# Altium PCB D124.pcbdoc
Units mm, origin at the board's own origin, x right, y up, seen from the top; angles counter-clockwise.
Board outline 29.56 x 21.95 mm, 2 copper layers (Top Layer, Bottom Layer); 1 components, 0 nets, 12 pads, 0 vias.
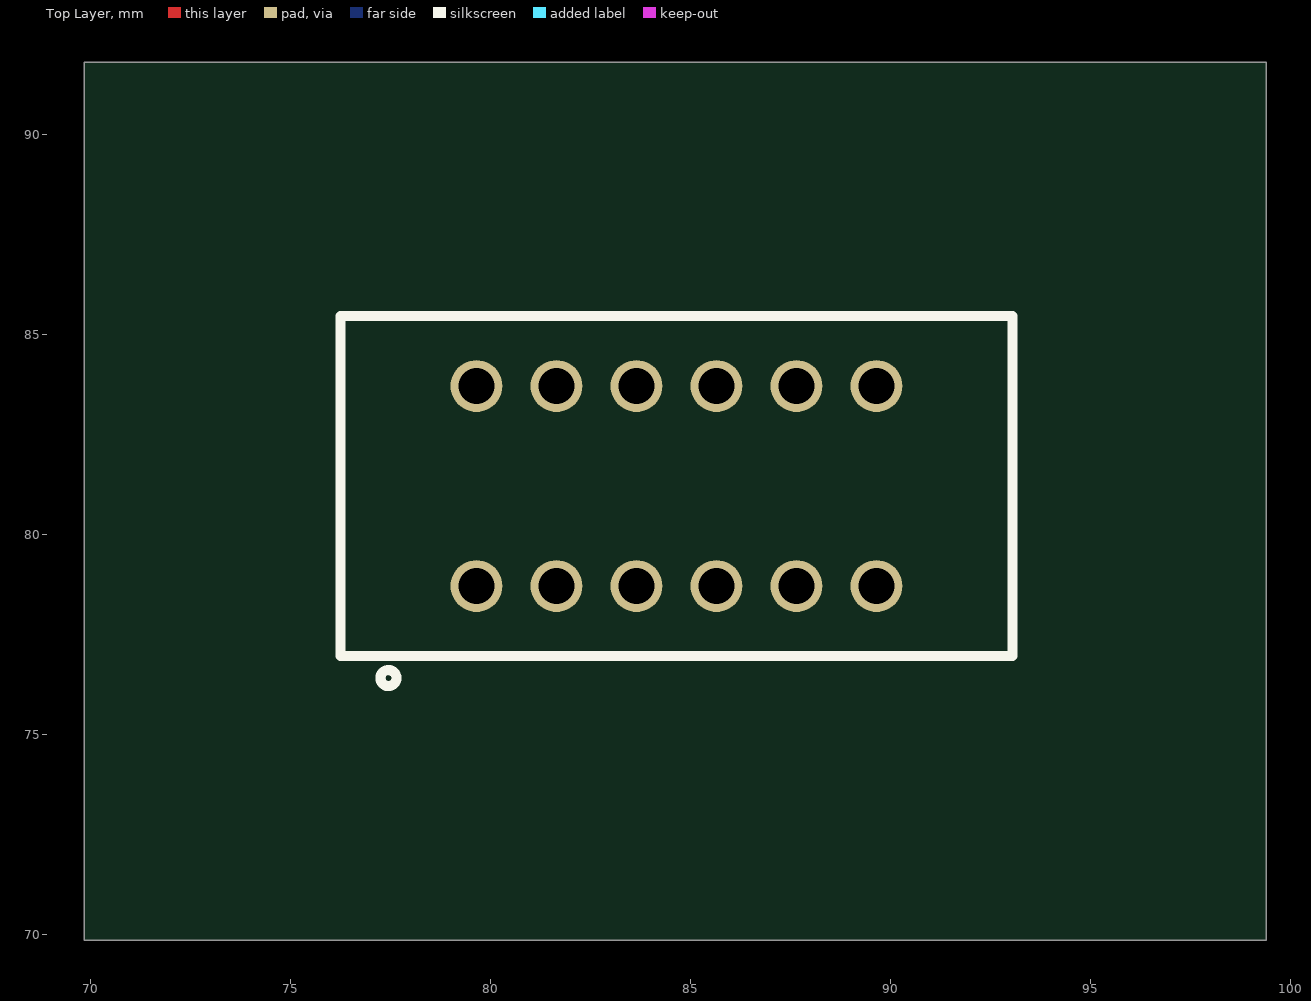
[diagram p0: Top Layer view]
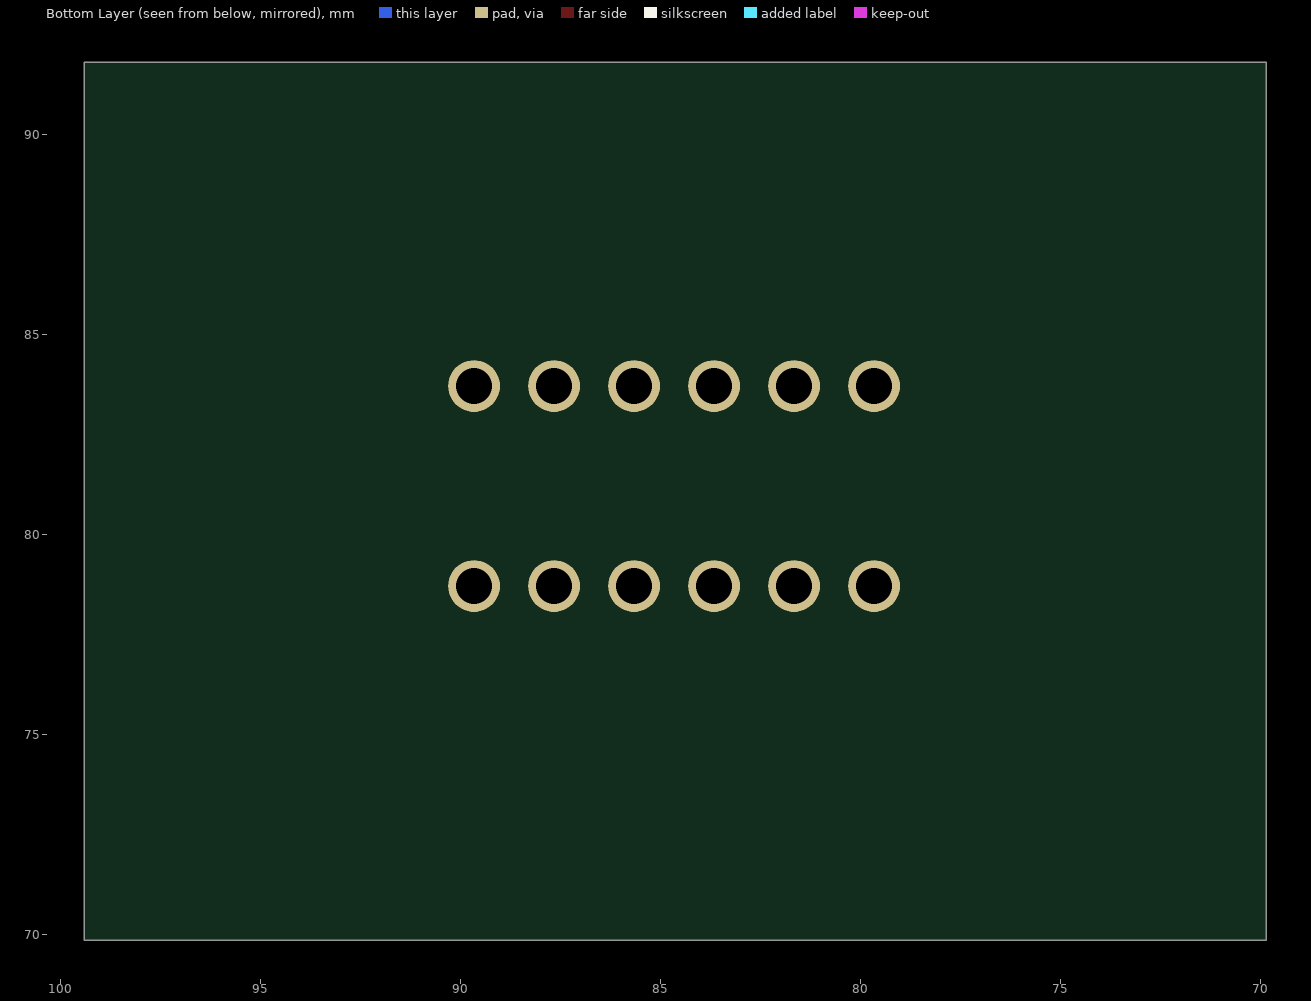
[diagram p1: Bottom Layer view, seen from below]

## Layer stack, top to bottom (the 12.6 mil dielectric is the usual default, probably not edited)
Top Layer: signal copper (thickness not stored)
Dielectric: dielectric 0.32, FR-4, Dk 4.8
Bottom Layer: signal copper (thickness not stored)

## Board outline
99.41,69.85 69.85,69.85 69.85,91.8 99.41,91.8

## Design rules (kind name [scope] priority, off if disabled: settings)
BoardOutlineClearance safeClearance [All] p0: genericclearance=0.254 ignorepadtopadclearanceinfootprint=FALSE except(0: Arc-SplitContinuation Track-SplitContinuation SMDPad-SplitContinuation THPad-SplitContinuation Via-SplitContinuation Fill-SplitContinuation Poly-SplitContinuation Region-SplitContinuation Text-SplitContinuation; 0.152: Track-CutoutEdge SMDPad-CutoutEdge THPad-CutoutEdge Via-CutoutEdge Fill-CutoutEdge Region-CutoutEdge; 0.3: Track-OutlineEdge SMDPad-OutlineEdge THPad-OutlineEdge Via-OutlineEdge Fill-OutlineEdge Region-OutlineEdge Poly-OutlineEdge Text-OutlineEdge)
Clearance safeClearance [All] p1: gap=0.178 ignorepadtopadclearanceinfootprint=FALSE except(0.152: Track-Track Track-SMDPad SMDPad-SMDPad Track-THPad SMDPad-THPad THPad-THPad Track-Via SMDPad-Via THPad-Via Via-Via Track-Fill SMDPad-Fill THPad-Fill Via-Fill Fill-Fill Track-Region SMDPad-Region THPad-Region Via-Region Fill-Region Region-Region Track-Poly SMDPad-Poly THPad-Poly Via-Poly Fill-Poly Region-Poly Poly-Poly Track-Text SMDPad-Text THPad-Text Via-Text Fill-Text Region-Text Poly-Text Text-Text; 0.175: Track-Hole SMDPad-Hole THPad-Hole Via-Hole Fill-Hole Region-Hole Poly-Hole Text-Hole Sheet-Hole; 0.3: Track-Sheet SMDPad-Sheet THPad-Sheet Via-Sheet Fill-Sheet Region-Sheet Poly-Sheet Text-Sheet)
DiffPairsRouting differentialPair [All] p1: maxuncoupledlength=10 minlimit=6 maxlimit=6 mostfreqgap=6 toplayer_minwidth=5 toplayer_prefwidth=10 toplayer_maxwidth=100 bottomlayer_minwidth=5 bottomlayer_prefwidth=10 bottomlayer_maxwidth=100
PasteMaskExpansion pasteMaskExpansion [All] p1: expansion=0
PlaneConnect innerPlane [All] p1: planeconnectstyle=Relief reliefexpansion=0.508 reliefentries=4 reliefconductorwidth=0.254 reliefairgap=0.254
PolygonConnect copperRegion [All] p1: connectstyle=Relief reliefentries=4 reliefconductorwidth=10 polygonreliefangle="90 Angle" airgapwidth=10
RoutingVias viaSize [All] p1: viastyle="Through Hole" holewidth=12.0078 minholewidth=11.811 maxholewidth=236.2204 width=24.0158 minwidth=19.685 maxwidth=393.7008
SolderMaskExpansion solderMaskExpansion [All] p1: useseparateexpansions=TRUE expansion=2 expansionbottom=2
Width trackWidth [All] p1: maxlimit=100 minlimit=5 preferedwidth=10

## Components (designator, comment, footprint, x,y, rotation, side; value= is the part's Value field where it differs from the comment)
? "DIP-18_16.8-W8.5-P1.78-LS4.8-BL" DIP-18_16.8-W8.5-P1.78-LS4.8-BL 84.66,81.2 r0 top

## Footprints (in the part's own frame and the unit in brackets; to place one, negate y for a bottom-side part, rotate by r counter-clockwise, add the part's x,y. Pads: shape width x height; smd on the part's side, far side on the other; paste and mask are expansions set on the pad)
DIP-18_16.8-W8.5-P1.78-LS4.8-BL [mm]
  round 1.3 hole 0.9: 1(-5,-2.5) 2(-3,-2.5) 3(-1,-2.5) 7(1,-2.5) 8(3,-2.5) 9(5,-2.5) 10(5,2.5) 11(3,2.5) 12(1,2.5) 16(-1,2.5) 17(-3,2.5) 18(-5,2.5)
  silkscreen extent -8.4,-5 8.4,4.25

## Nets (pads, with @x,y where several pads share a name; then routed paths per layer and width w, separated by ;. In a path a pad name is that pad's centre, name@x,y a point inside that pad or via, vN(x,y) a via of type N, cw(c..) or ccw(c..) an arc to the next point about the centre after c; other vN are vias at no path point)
pads on no net: ?.1 ?.2 ?.3 ?.7 ?.8 ?.9 ?.10 ?.11 ?.12 ?.16 ?.17 ?.18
